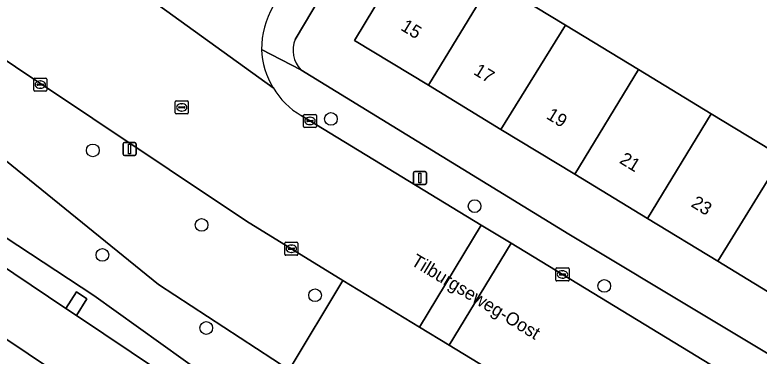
# Model space of a CAD drawing. Extents: x 158352 to 159489, y 383828 to 384603.
# Drawn here: x 158789.9 to 158847.1, y 383937.1 to 383963.3 of the extents above; entities that cross this region are included whole.
import ezdxf

# ---------------------------------------------------------------- set-up
doc = ezdxf.new("R2010")
doc.units = 0
for name, color, linetype in [('IMGEO_Berm_groen', 7, 'Continuous'), ('IMGEO_Boom', 7, 'Continuous'), ('IMGEO_Erf', 7, 'Continuous'), ('IMGEO_Groenvoorziening', 7, 'Continuous'), ('IMGEO_Kolk', 7, 'Continuous'), ('IMGEO_Lichtmast', 7, 'Continuous'), ('IMGEO_Openbare_ruimte_label', 7, 'Continuous'), ('IMGEO_Pand', 7, 'Continuous'), ('IMGEO_Pand_nummerreeks', 7, 'Continuous'), ('IMGEO_Rijbaan_lokaal_open', 7, 'Continuous'), ('IMGEO_Rijbaan_regionaal_gesloten', 7, 'Continuous'), ('IMGEO_Rioolput', 7, 'Continuous'), ('IMGEO_Voetpad_open', 7, 'Continuous')]:
    doc.layers.add(name, color=color, linetype=linetype)

msp = doc.modelspace()

# ---------------------------------------------------------------- linework, layer by layer
at = {"layer": 'IMGEO_Berm_groen'}
for points in [[(158809.311, 383924.969), (158764.39, 383955.088), (158755.227, 383961.2), (158745.974, 383967.224), (158723.089, 383981.844), (158660.628, 384021.748)], [(158727.655, 383984.329), (158743.756, 383974.053), (158744.565, 383975.319), (158745.367, 383974.792), (158744.558, 383973.512), (158753.414, 383967.794), (158760.526, 383963.092), (158761.33, 383964.373), (158762.131, 383963.844), (158761.32, 383962.566), (158777.216, 383951.947), (158778.052, 383953.227), (158778.841, 383952.68), (158778, 383951.421), (158793.85, 383940.776), (158794.658, 383942.052), (158795.461, 383941.525), (158794.653, 383940.245), (158809.276, 383930.441), (158809.728, 383931.93), (158795.981, 383941.779), (158765.871, 383961.56), (158707.358, 384000)]]:
    msp.add_lwpolyline(points, dxfattribs=at)
at = {"layer": 'IMGEO_Boom'}
for centre in [(158814.204, 383955.336), (158795.915, 383952.915), (158825.235, 383948.633), (158804.27, 383947.189), (158796.654, 383944.886), (158835.201, 383942.507), (158812.983, 383941.792), (158804.629, 383939.276)]:
    msp.add_circle(centre, 0.489, dxfattribs=at)
at = {"layer": 'IMGEO_Erf'}
for points in [[(158849.616, 383965.92), (158846.84, 383967.608), (158845.169, 383964.859), (158842.366, 383966.562), (158839.602, 383968.242), (158841.273, 383970.991), (158835.6, 383974.441), (158833.929, 383971.692), (158831.114, 383973.403), (158828.362, 383975.075), (158830.033, 383977.824), (158827.393, 383979.426), (158822.843, 383971.94), (158828.233, 383968.664), (158826.585, 383965.952), (158832.219, 383962.527), (158837.825, 383959.119), (158843.416, 383955.721), (158848.864, 383952.409)], [(158849.585, 383940.963), (158843.929, 383944.401), (158838.53, 383947.683), (158832.926, 383951.089), (158827.264, 383954.531), (158821.699, 383957.914), (158816.018, 383961.367), (158817.576, 383963.931), (158814.431, 383965.842), (158814.158, 383966.008), (158811.467, 383961.443)], [(158811.894, 383959.106), (158832.465, 383946.483), (158864.328, 383927.368), (158866.364, 383930.763), (158860.79, 383934.151), (158855.261, 383937.512), (158849.585, 383940.963)]]:
    msp.add_lwpolyline(points, dxfattribs=at)
msp.add_arc((158813.417, 383960.592), 2.128, 156.4156, 224.2933, dxfattribs=at)
at = {"layer": 'IMGEO_Groenvoorziening'}
for points in [[(158613.197, 384066.952), (158612.294, 384067.106), (158609.144, 384064.921), (158606.221, 384062.826), (158611.3, 384058.953), (158613.62, 384057.184), (158614.378, 384057.858), (158626.962, 384050.112), (158651.483, 384034.675), (158661.741, 384028.584), (158677.929, 384018.316), (158707.358, 384000), (158765.871, 383961.56), (158795.981, 383941.779), (158809.728, 383931.93), (158811, 383936.053), (158800.948, 383942.61), (158788.302, 383952.844), (158769.011, 383966.352), (158753.016, 383977.553), (158718.365, 384000), (158666.397, 384033.665)], [(158870.424, 383909.269), (158823.283, 383937.959), (158821.005, 383939.346), (158815.119, 383942.928), (158811, 383936.053), (158815.357, 383932.963), (158859.991, 383902.143)]]:
    msp.add_lwpolyline(points, dxfattribs=at)
msp.add_lwpolyline([(158772.196, 383971.212), (158772.161, 383971.159), (158769.011, 383966.352), (158788.302, 383952.844), (158800.948, 383942.61), (158811, 383936.053), (158815.119, 383942.928), (158807.716, 383947.485)], close=True, dxfattribs=at)
at = {"layer": 'IMGEO_Kolk'}
for p, q in [((158791.454, 383958.467), (158792.306, 383958.467)), ((158791.379, 383957.541), (158791.379, 383958.393)), ((158791.638, 383957.961), (158791.638, 383957.973)), ((158792.076, 383957.924), (158791.678, 383957.924)), ((158791.681, 383958.01), (158792.079, 383958.01)), ((158791.867, 383958.247), (158791.892, 383958.247)), ((158792.122, 383957.973), (158792.122, 383957.961)), ((158792.38, 383958.393), (158792.38, 383957.541)), ((158792.306, 383957.467), (158791.454, 383957.467)), ((158791.89, 383957.687), (158791.865, 383957.687)), ((158812.094, 383954.755), (158812.094, 383955.607)), ((158812.169, 383955.681), (158813.021, 383955.681)), ((158813.095, 383955.607), (158813.095, 383954.755)), ((158812.353, 383955.175), (158812.353, 383955.187)), ((158812.791, 383955.138), (158812.393, 383955.138)), ((158812.396, 383955.224), (158812.794, 383955.224)), ((158812.582, 383955.461), (158812.607, 383955.461)), ((158812.837, 383955.187), (158812.837, 383955.175)), ((158813.021, 383954.681), (158812.169, 383954.681)), ((158812.605, 383954.901), (158812.58, 383954.901)), ((158810.739, 383945.86), (158811.591, 383945.86)), ((158810.664, 383944.934), (158810.664, 383945.786)), ((158810.923, 383945.354), (158810.923, 383945.366)), ((158811.361, 383945.317), (158810.963, 383945.317)), ((158810.966, 383945.403), (158811.364, 383945.403)), ((158811.152, 383945.64), (158811.177, 383945.64)), ((158811.407, 383945.366), (158811.407, 383945.354)), ((158811.665, 383945.786), (158811.665, 383944.934)), ((158811.591, 383944.86), (158810.739, 383944.86)), ((158811.175, 383945.08), (158811.15, 383945.08)), ((158831.489, 383942.96), (158831.489, 383943.812)), ((158831.564, 383943.886), (158832.416, 383943.886)), ((158831.977, 383943.666), (158832.002, 383943.666)), ((158832.49, 383943.812), (158832.49, 383942.96)), ((158831.748, 383943.38), (158831.748, 383943.392)), ((158832.186, 383943.343), (158831.788, 383943.343)), ((158831.791, 383943.429), (158832.189, 383943.429)), ((158832, 383943.106), (158831.975, 383943.106)), ((158832.232, 383943.392), (158832.232, 383943.38)), ((158832.416, 383942.886), (158831.564, 383942.886))]:
    msp.add_line(p, q, dxfattribs=at)
for points in [[(158791.454, 383958.467), (158792.306, 383958.467)], [(158791.379, 383957.541), (158791.379, 383958.393)], [(158792.38, 383958.393), (158792.38, 383957.541)], [(158792.306, 383957.467), (158791.454, 383957.467)], [(158812.094, 383954.755), (158812.094, 383955.607)], [(158812.169, 383955.681), (158813.021, 383955.681)], [(158813.095, 383955.607), (158813.095, 383954.755)], [(158813.021, 383954.681), (158812.169, 383954.681)], [(158810.739, 383945.86), (158811.591, 383945.86)], [(158810.664, 383944.934), (158810.664, 383945.786)], [(158811.665, 383945.786), (158811.665, 383944.934)], [(158811.591, 383944.86), (158810.739, 383944.86)], [(158831.489, 383942.96), (158831.489, 383943.812)], [(158831.564, 383943.886), (158832.416, 383943.886)], [(158832.49, 383943.812), (158832.49, 383942.96)], [(158832.416, 383942.886), (158831.564, 383942.886)]]:
    msp.add_lwpolyline(points, dxfattribs=at)
for centre, radius, start, end in [((158791.456, 383958.391), 0.0765, 91.552, 178.448), ((158791.456, 383958.391), 0.0765, 91.552, 178.448), ((158792.304, 383958.391), 0.0765, 1.552, 88.448), ((158792.304, 383958.391), 0.0765, 1.552, 88.448), ((158791.678, 383957.97), 0.0403, 85.8775, 175.7526), ((158791.675, 383957.96), 0.0366, 178.938, 274.7102), ((158792.079, 383957.967), 0.043, 264.8664, 352.4533), ((158792.083, 383957.972), 0.0386, 1.7309, 96.639), ((158791.456, 383957.543), 0.0765, 181.552, 268.448), ((158791.456, 383957.543), 0.0765, 181.552, 268.448), ((158792.304, 383957.543), 0.0765, 271.552, 358.448), ((158792.304, 383957.543), 0.0765, 271.552, 358.448), ((158812.171, 383955.605), 0.0765, 91.552, 178.448), ((158812.171, 383955.605), 0.0765, 91.552, 178.448), ((158813.019, 383955.605), 0.0765, 1.552, 88.448), ((158813.019, 383955.605), 0.0765, 1.552, 88.448), ((158812.393, 383955.184), 0.0403, 85.8775, 175.7526), ((158812.39, 383955.174), 0.0366, 178.938, 274.7102), ((158812.794, 383955.181), 0.043, 264.8664, 352.4533), ((158812.798, 383955.186), 0.0386, 1.7309, 96.639), ((158812.171, 383954.757), 0.0765, 181.552, 268.448), ((158812.171, 383954.757), 0.0765, 181.552, 268.448), ((158813.019, 383954.757), 0.0765, 271.552, 358.448), ((158813.019, 383954.757), 0.0765, 271.552, 358.448), ((158810.741, 383945.784), 0.0765, 91.552, 178.448), ((158810.741, 383945.784), 0.0765, 91.552, 178.448), ((158811.589, 383945.784), 0.0765, 1.552, 88.448), ((158811.589, 383945.784), 0.0765, 1.552, 88.448), ((158810.963, 383945.363), 0.0403, 85.8775, 175.7526), ((158810.96, 383945.353), 0.0366, 178.938, 274.7102), ((158811.364, 383945.36), 0.043, 264.8664, 352.4533), ((158811.368, 383945.365), 0.0386, 1.7309, 96.639), ((158810.741, 383944.936), 0.0765, 181.552, 268.448), ((158810.741, 383944.936), 0.0765, 181.552, 268.448), ((158811.589, 383944.936), 0.0765, 271.552, 358.448), ((158811.589, 383944.936), 0.0765, 271.552, 358.448), ((158831.566, 383943.81), 0.0765, 91.552, 178.448), ((158831.566, 383943.81), 0.0765, 91.552, 178.448), ((158832.414, 383943.81), 0.0765, 1.552, 88.448), ((158832.414, 383943.81), 0.0765, 1.552, 88.448), ((158831.788, 383943.389), 0.0403, 85.8775, 175.7526), ((158831.785, 383943.379), 0.0366, 178.938, 274.7102), ((158832.189, 383943.386), 0.043, 264.8664, 352.4533), ((158832.193, 383943.391), 0.0386, 1.7309, 96.639), ((158831.566, 383942.962), 0.0765, 181.552, 268.448), ((158831.566, 383942.962), 0.0765, 181.552, 268.448), ((158832.414, 383942.962), 0.0765, 271.552, 358.448), ((158832.414, 383942.962), 0.0765, 271.552, 358.448)]:
    msp.add_arc(centre, radius, start, end, dxfattribs=at)
for centre, major_axis, ratio, start_param, end_param in [((158791.866, 383957.967), (-0.387, 0.002), 0.722429, 4.712389, 7.853982), ((158791.891, 383957.967), (-0.39, 0.002), 0.717154, 1.570796, 4.712389), ((158812.581, 383955.181), (-0.387, 0.002), 0.722429, 4.712389, 7.853982), ((158812.606, 383955.181), (-0.39, 0.002), 0.717154, 1.570796, 4.712389), ((158811.151, 383945.36), (-0.387, 0.002), 0.722429, 4.712389, 7.853982), ((158811.176, 383945.36), (-0.39, 0.002), 0.717154, 1.570796, 4.712389), ((158831.976, 383943.386), (-0.387, 0.002), 0.722429, 4.712389, 7.853982), ((158832.001, 383943.386), (-0.39, 0.002), 0.717154, 1.570796, 4.712389)]:
    msp.add_ellipse(centre, major_axis=major_axis, ratio=ratio, start_param=start_param, end_param=end_param, dxfattribs=at)
at = {"layer": 'IMGEO_Lichtmast'}
for p, q in [((158798.242, 383952.629), (158798.242, 383953.429)), ((158798.242, 383953.429), (158798.242, 383952.629)), ((158798.342, 383953.529), (158799.132, 383953.529)), ((158799.132, 383953.529), (158798.342, 383953.529)), ((158799.232, 383953.429), (158799.232, 383952.629)), ((158799.232, 383952.629), (158799.232, 383953.429)), ((158799.132, 383952.529), (158798.342, 383952.529)), ((158798.342, 383952.529), (158799.132, 383952.529)), ((158820.542, 383950.398), (158820.542, 383951.198)), ((158820.542, 383951.198), (158820.542, 383950.398)), ((158820.642, 383951.298), (158821.432, 383951.298)), ((158821.432, 383951.298), (158820.642, 383951.298)), ((158821.532, 383951.198), (158821.532, 383950.398)), ((158821.532, 383950.398), (158821.532, 383951.198)), ((158821.432, 383950.298), (158820.642, 383950.298)), ((158820.642, 383950.298), (158821.432, 383950.298))]:
    msp.add_line(p, q, dxfattribs=at)
for points in [[(158798.662, 383953.404), (158798.812, 383953.404), (158798.812, 383952.654), (158798.662, 383952.654), (158798.662, 383953.404)], [(158820.962, 383951.173), (158821.112, 383951.173), (158821.112, 383950.423), (158820.962, 383950.423), (158820.962, 383951.173)]]:
    msp.add_lwpolyline(points, dxfattribs=at)
for centre, start, end in [((158798.342, 383953.429), 90, 180), ((158798.342, 383953.429), 90, 180), ((158799.132, 383953.429), 0, 90), ((158799.132, 383953.429), 360, 90), ((158798.342, 383952.629), 180, 270), ((158798.342, 383952.629), 180, 270), ((158799.132, 383952.629), 270, 0), ((158799.132, 383952.629), 270, 0), ((158820.642, 383951.198), 90, 180), ((158820.642, 383951.198), 90, 180), ((158821.432, 383951.198), 0, 90), ((158821.432, 383951.198), 360, 90), ((158820.642, 383950.398), 180, 270), ((158820.642, 383950.398), 180, 270), ((158821.432, 383950.398), 270, 0), ((158821.432, 383950.398), 270, 0)]:
    msp.add_arc(centre, 0.1, start, end, dxfattribs=at)
at = {"layer": 'IMGEO_Pand'}
for points in [[(158827.393, 383979.426), (158825.424, 383980.625), (158823.318, 383980.566), (158814.431, 383965.842), (158817.576, 383963.931), (158816.018, 383961.367), (158821.699, 383957.914), (158826.585, 383965.952), (158828.233, 383968.664), (158822.843, 383971.94)], [(158827.264, 383954.531), (158832.219, 383962.527), (158826.585, 383965.952), (158821.699, 383957.914)], [(158832.926, 383951.089), (158837.825, 383959.119), (158832.219, 383962.527), (158827.264, 383954.531)], [(158832.926, 383951.089), (158838.53, 383947.683), (158843.416, 383955.721), (158837.825, 383959.119)], [(158843.416, 383955.721), (158838.53, 383947.683), (158843.929, 383944.401), (158848.864, 383952.409)], [(158854.471, 383949.001), (158856.02, 383951.549), (158856.16, 383951.78), (158850.57, 383955.177), (158848.864, 383952.409), (158843.929, 383944.401), (158849.585, 383940.963)]]:
    msp.add_lwpolyline(points, close=True, dxfattribs=at)
at = {"layer": 'IMGEO_Rijbaan_lokaal_open'}
for points in [[(158797.412, 383965.088), (158772.851, 383981.561), (158767.881, 383974.094), (158772.196, 383971.212), (158807.716, 383947.485), (158815.119, 383942.928), (158821.005, 383939.346), (158825.751, 383947.179), (158811.929, 383955.585)], [(158800.948, 383964.073), (158809.759, 383957.733)], [(158809.759, 383957.733), (158800.948, 383964.073)]]:
    msp.add_lwpolyline(points, dxfattribs=at)
for points in [[(158823.283, 383937.959), (158828.048, 383945.782), (158825.751, 383947.179), (158821.005, 383939.346)], [(158823.283, 383937.959), (158870.424, 383909.269), (158875.147, 383917.123), (158849.664, 383932.637), (158828.048, 383945.782)], [(158793.85, 383940.776), (158794.653, 383940.245), (158795.461, 383941.525), (158794.658, 383942.052)]]:
    msp.add_lwpolyline(points, close=True, dxfattribs=at)
for centre, radius, start, end in [((158815.385, 383960.685), 6.512, 149.586, 180.2597), ((158815.091, 383960.945), 6.225, 182.6704, 211.066), ((158815.087, 383960.946), 6.222, 211.0877, 239.4961)]:
    msp.add_arc(centre, radius, start, end, dxfattribs=at)
at = {"layer": 'IMGEO_Rijbaan_regionaal_gesloten'}
for points in [[(158660.628, 384021.748), (158723.089, 383981.844), (158745.974, 383967.224), (158755.227, 383961.2), (158764.39, 383955.088), (158809.311, 383924.969)], [(158844.225, 383906.095), (158843.424, 383906.676), (158827.883, 383917.76), (158827.089, 383918.32), (158811.325, 383929.071), (158810.523, 383929.605), (158809.276, 383930.441), (158794.653, 383940.245), (158793.85, 383940.776), (158778, 383951.421), (158777.216, 383951.947), (158761.32, 383962.566), (158760.526, 383963.092), (158753.414, 383967.794), (158744.558, 383973.512), (158743.756, 383974.053), (158727.655, 383984.329)]]:
    msp.add_lwpolyline(points, dxfattribs=at)
at = {"layer": 'IMGEO_Rioolput'}
for p, q in [((158802.321, 383956.716), (158803.173, 383956.716)), ((158802.246, 383955.79), (158802.246, 383956.642)), ((158802.505, 383956.21), (158802.505, 383956.222)), ((158802.943, 383956.173), (158802.545, 383956.173)), ((158802.548, 383956.259), (158802.946, 383956.259)), ((158802.734, 383956.496), (158802.759, 383956.496)), ((158802.989, 383956.222), (158802.989, 383956.21)), ((158803.247, 383956.642), (158803.247, 383955.79)), ((158803.173, 383955.716), (158802.321, 383955.716)), ((158802.757, 383955.936), (158802.732, 383955.936))]:
    msp.add_line(p, q, dxfattribs=at)
for points in [[(158802.321, 383956.716), (158803.173, 383956.716)], [(158802.246, 383955.79), (158802.246, 383956.642)], [(158803.247, 383956.642), (158803.247, 383955.79)], [(158803.173, 383955.716), (158802.321, 383955.716)]]:
    msp.add_lwpolyline(points, dxfattribs=at)
for centre, radius, start, end in [((158802.323, 383956.64), 0.0765, 91.552, 178.448), ((158802.323, 383956.64), 0.0765, 91.552, 178.448), ((158803.171, 383956.64), 0.0765, 1.552, 88.448), ((158803.171, 383956.64), 0.0765, 1.552, 88.448), ((158802.545, 383956.219), 0.0403, 85.8775, 175.7526), ((158802.542, 383956.209), 0.0366, 178.938, 274.7102), ((158802.946, 383956.216), 0.043, 264.8664, 352.4533), ((158802.95, 383956.221), 0.0386, 1.7309, 96.639), ((158802.323, 383955.792), 0.0765, 181.552, 268.448), ((158802.323, 383955.792), 0.0765, 181.552, 268.448), ((158803.171, 383955.792), 0.0765, 271.552, 358.448), ((158803.171, 383955.792), 0.0765, 271.552, 358.448)]:
    msp.add_arc(centre, radius, start, end, dxfattribs=at)
for centre, major_axis, ratio, start_param, end_param in [((158802.733, 383956.216), (-0.387, 0.002), 0.722429, 4.712389, 7.853982), ((158802.758, 383956.216), (-0.39, 0.002), 0.717154, 1.570796, 4.712389)]:
    msp.add_ellipse(centre, major_axis=major_axis, ratio=ratio, start_param=start_param, end_param=end_param, dxfattribs=at)
at = {"layer": 'IMGEO_Voetpad_open'}
for points in [[(158811.467, 383961.443), (158814.158, 383966.008), (158822.729, 383980.822)], [(158832.465, 383946.483), (158811.894, 383959.106), (158808.873, 383960.655)], [(158808.873, 383960.655), (158811.894, 383959.106)], [(158811.929, 383955.585), (158825.751, 383947.179), (158828.048, 383945.782), (158849.664, 383932.637), (158875.147, 383917.123), (158877.427, 383915.735), (158890.133, 383907.999)], [(158894.205, 383907.454), (158893.501, 383909.418), (158888.633, 383912.412), (158886.902, 383913.477), (158880.931, 383917.315), (158872.913, 383922.218), (158865.975, 383926.38), (158865.759, 383926.51), (158865.658, 383926.571), (158864.328, 383927.368), (158832.465, 383946.483)]]:
    msp.add_lwpolyline(points, dxfattribs=at)
for centre, radius, start, end in [((158815.385, 383960.685), 6.512, 149.586, 180.2597), ((158813.417, 383960.592), 2.128, 156.4156, 224.2933), ((158815.091, 383960.945), 6.225, 182.6704, 211.066), ((158815.087, 383960.946), 6.222, 211.0877, 239.4961)]:
    msp.add_arc(centre, radius, start, end, dxfattribs=at)

# ---------------------------------------------------------------- texts
at = {"layer": 'IMGEO_Openbare_ruimte_label'}
msp.add_text('Tilburgseweg-Oost', height=1, rotation=328.7905, dxfattribs=at).set_placement((158820.284, 383944.163))
at = {"layer": 'IMGEO_Pand_nummerreeks'}
for s, rotation, p in [('15', 328.705, (158819.495, 383962.202)), ('17', 328.7057, (158825.09, 383958.801)), ('19', 328.7057, (158830.684, 383955.401)), ('21', 328.7057, (158836.296, 383951.99)), ('23', 328.7057, (158841.794, 383948.648))]:
    msp.add_text(s, height=1, rotation=rotation, dxfattribs=at).set_placement(p)

doc.saveas('drawing.dxf')
